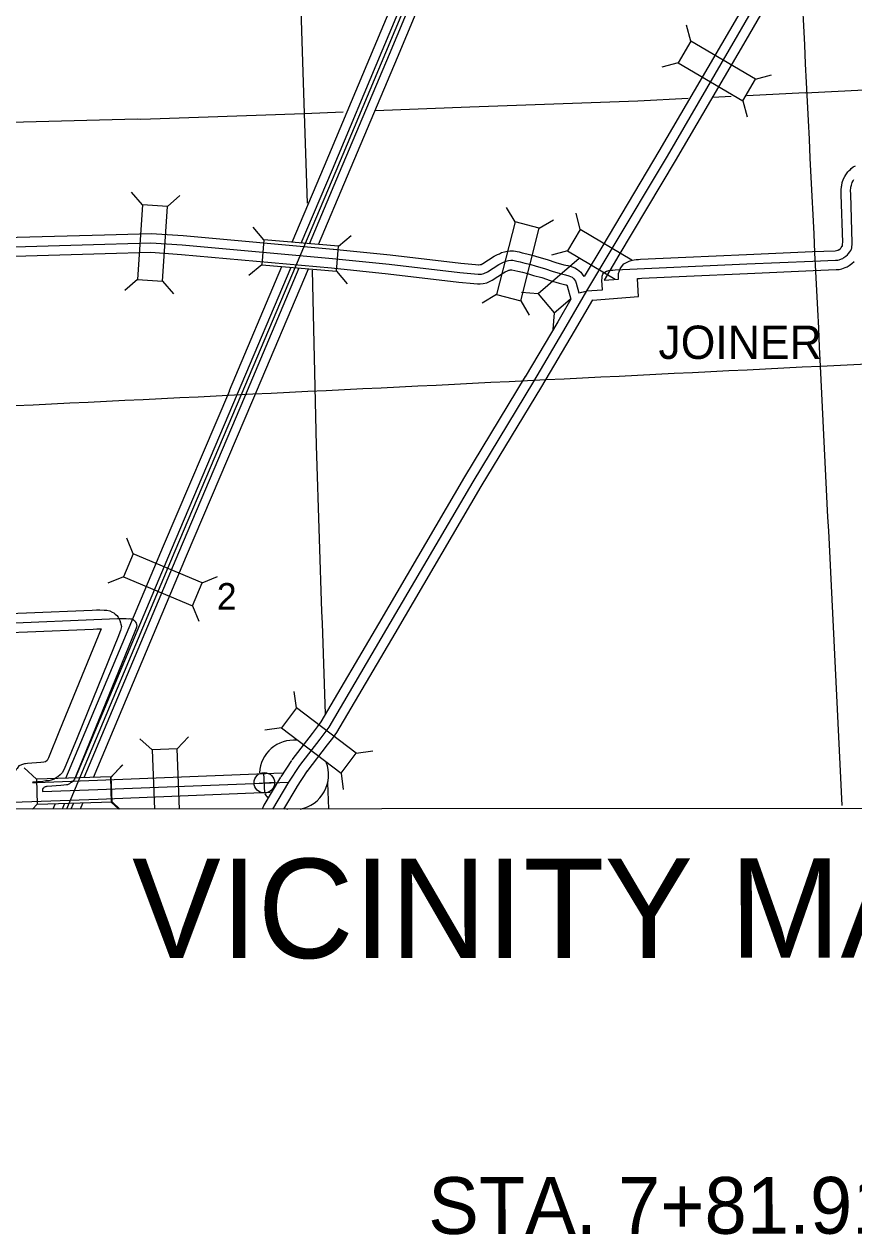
# Model space of a CAD drawing. Extents: x 2520745 to 2582119, y -1491628 to -1461664.
# Drawn here: x 2524549 to 2528934, y -1474299 to -1467904 of the extents above; entities that cross this region are included whole.
import ezdxf

# ---------------------------------------------------------------- set-up
doc = ezdxf.new("R2010")
doc.units = 0
for name, color, linetype in [('1', 7, 'Continuous'), ('10', 7, 'Continuous'), ('15', 7, 'Continuous'), ('19', 7, 'Continuous'), ('20', 7, 'Continuous'), ('24', 7, 'Continuous'), ('26', 7, 'Continuous'), ('4', 7, 'Continuous'), ('59', 7, 'Continuous'), ('6', 7, 'Continuous'), ('60', 7, 'Continuous'), ('R_Draft', 7, 'Continuous')]:
    doc.layers.add(name, color=color, linetype=linetype)

msp = doc.modelspace()

# ---------------------------------------------------------------- linework, layer by layer
at = {"layer": '1'}
msp.add_lwpolyline([(2520744.9, -1463342.8), (2532121.5, -1463335.8), (2532126.8, -1472046.5), (2520750.2, -1472053.4)], close=True, dxfattribs=at)
at = {"layer": '10'}
for points in [[(2528716, -1469105.2), (2528835.2, -1469100.9), (2528842.2, -1469100.4), (2528843.4, -1469100.1), (2528850.9, -1469097.5), (2528852.2, -1469096.8), (2528854.5, -1469095.5), (2528861.8, -1469090), (2528865.1, -1469087.4), (2528867.7, -1469084.1), (2528873.4, -1469077.2), (2528873.7, -1469076.8), (2528874, -1469073.3), (2528875.2, -1469065), (2528875.8, -1469058), (2528867.8, -1468803.4), (2528866.8, -1468780.4), (2528869, -1468761.6), (2528870.1, -1468756.1), (2528872.7, -1468741.2), (2528880.5, -1468720.8), (2528886.2, -1468709.6), (2528891.2, -1468699.1), (2528903, -1468683.6), (2528910.2, -1468676.4), (2528915.8, -1468671.2), (2528921, -1468666.7), (2528930.7, -1468658.4), (2528943.4, -1468652.4)], [(2524312.7, -1469035.1), (2524973.8, -1469016.2), (2525219.5, -1469009.1), (2525388.5, -1469020.3), (2526182.9, -1469091.8)], [(2526183.5, -1469091.9), (2526483.8, -1469122.7), (2526857.3, -1469166.7), (2526934.6, -1469173.7), (2526950.4, -1469175.4), (2526952.3, -1469175.4), (2526959.3, -1469174.5), (2526963.6, -1469173.7), (2526973.3, -1469169.2), (2527032.6, -1469129.5), (2527051.1, -1469121), (2527061.6, -1469116.5), (2527072.5, -1469111), (2527088.4, -1469105.9), (2527102.2, -1469103.1), (2527116.9, -1469101.6), (2527136, -1469100.8), (2527164.7, -1469107.2), (2527182, -1469111.6), (2527205.9, -1469117.4), (2527234.7, -1469124), (2527270, -1469135), (2527313.9, -1469147.3), (2527359.6, -1469162.2), (2527401.8, -1469174.8), (2527422.7, -1469179.7), (2527444.7, -1469185.7), (2527459.1, -1469191.6), (2527473.2, -1469200), (2527482.8, -1469207.7), (2527490.7, -1469215), (2527498.6, -1469224.2), (2527506.9, -1469236.8)], [(2528045.5, -1469135.3), (2528367, -1469120.5), (2528715.6, -1469105.2)], [(2524315.9, -1469135.1), (2524976.7, -1469116.1), (2525217.6, -1469109.2), (2525380.7, -1469120), (2526174, -1469191.4)], [(2527690.2, -1469250.9), (2527690.8, -1469238), (2527690.7, -1469221.2), (2527695.8, -1469206.5), (2527699.7, -1469197), (2527706, -1469185.4), (2527717.9, -1469170.9), (2527732.4, -1469162.9), (2527747.4, -1469155.9), (2527756.9, -1469153.3), (2527763.7, -1469151.3), (2527772.7, -1469149.5), (2527783.8, -1469147.5), (2527795.5, -1469147), (2527807, -1469146.2), (2528045.5, -1469135.3)], [(2528719.7, -1469205.1), (2528840.5, -1469200.8), (2528856.1, -1469199.6), (2528870.7, -1469196.6), (2528888.8, -1469190.1), (2528898.5, -1469185.6), (2528910, -1469179), (2528923.3, -1469168.9), (2528936.7, -1469158.1)], [(2526173.3, -1469191.3), (2526472.8, -1469222.1), (2526846.9, -1469266.2), (2526924.8, -1469273.3), (2526945.1, -1469275.4), (2526958.6, -1469275.4), (2526974.7, -1469273.3), (2526994.2, -1469269.8), (2527022.5, -1469256.6), (2527081.7, -1469217), (2527092, -1469212.3), (2527103.8, -1469207.2), (2527110.4, -1469203.8), (2527113.6, -1469202.8), (2527117.1, -1469202.1), (2527124.2, -1469201.4), (2527127.1, -1469201.3), (2527141.5, -1469204.5), (2527157.8, -1469208.6), (2527183, -1469214.8), (2527208.8, -1469220.6), (2527241.7, -1469230.9), (2527284.8, -1469243), (2527329.7, -1469257.7), (2527375.9, -1469271.4), (2527398.1, -1469276.7), (2527412.5, -1469280.6), (2527414.3, -1469281.3), (2527416, -1469282.3), (2527417.5, -1469283.5), (2527418.4, -1469284.3), (2527418.9, -1469286.1), (2527437.9, -1469357)], [(2527795.6, -1469343.4), (2527790.3, -1469250.2), (2527790.4, -1469247.9), (2527791.4, -1469247.7), (2527794.8, -1469247.1), (2527801.1, -1469246.8), (2527812.8, -1469246), (2528050.1, -1469235.2)], [(2528050.1, -1469235.2), (2528371.5, -1469220.4), (2528720, -1469205.1)], [(2527615.3, -1469256.5), (2527690.2, -1469250.9)], [(2527553.5, -1469361.3), (2527795.6, -1469343.4)], [(2522613.1, -1471078.5), (2523482, -1471051.5), (2524373.6, -1471021.4), (2524561.8, -1471013.8)], [(2524561.8, -1471013.8), (2524907.8, -1470999.7), (2524931.4, -1470998.2), (2524948.3, -1470998.6), (2524971.7, -1470999.3), (2524985.2, -1471000.6), (2525001.5, -1471003.3), (2525014.7, -1471009.6), (2525023, -1471014.1), (2525029.6, -1471020.1), (2525037.5, -1471026.8), (2525037.9, -1471027.3)], [(2525037.9, -1471027.3), (2525045.1, -1471036.6), (2525049.5, -1471044), (2525055.1, -1471054), (2525058.7, -1471066.1), (2525059.9, -1471073.4), (2525062.8, -1471086.8), (2525058.3, -1471108), (2525055.3, -1471116.7), (2525048.2, -1471135.4), (2524828.6, -1471674)], [(2522605.7, -1471178.8), (2523485.2, -1471151.5), (2524377.3, -1471121.3), (2524565.9, -1471113.7)], [(2524565.9, -1471113.7), (2524912.9, -1471099.6), (2524933.3, -1471098.3), (2524941.3, -1471098.5)], [(2524941.3, -1471098.5), (2524945.8, -1471098.6), (2524953, -1471098.8), (2524955.1, -1471099), (2524736, -1471636.2)], [(2524736, -1471636.2), (2524677.3, -1471779.9), (2524671.2, -1471794.5), (2524662.1, -1471801.8), (2524653.3, -1471802.2), (2524636.1, -1471804.7), (2524566.2, -1471809.6), (2524556.7, -1471810.7), (2524550.6, -1471812.3), (2524544.8, -1471813.8), (2524521.2, -1471822.9), (2524511.7, -1471836.1), (2524506.6, -1471841.6), (2524498.2, -1471857.7), (2524495.2, -1471872.7), (2524489.4, -1472014.5)], [(2524828.6, -1471674), (2524769.7, -1471818.2), (2524758.9, -1471844), (2524749.6, -1471858.4), (2524739.8, -1471869.2), (2524726.4, -1471880), (2524721, -1471882.7), (2524717.9, -1471885.2), (2524706.7, -1471892.8), (2524691.8, -1471898), (2524679.7, -1471901), (2524662.9, -1471901.8), (2524646.9, -1471904.2), (2524593.8, -1471907.9), (2524593.7, -1471910.7)], [(2524593.7, -1471910.7), (2524613.6, -1471910)], [(2524613.6, -1471910), (2524936.4, -1471898.4)], [(2524936.4, -1471897.8), (2525913.3, -1471859.2)], [(2524940.3, -1471997.7), (2525849.7, -1471961.8)], [(2524940.3, -1471997.7), (2525849.7, -1471961.8)], [(2524489.4, -1472014.5), (2524940.3, -1471998.4)]]:
    msp.add_lwpolyline(points, dxfattribs=at)
at = {"layer": '15'}
for points in [[(2528611.7, -1467485.9), (2528591.4, -1467507), (2528560.4, -1467530.3), (2528535.5, -1467557.2), (2528516, -1467575.6), (2528500.1, -1467592.7), (2528489.1, -1467606.8), (2528479, -1467617.8), (2528467, -1467630.1), (2528456.5, -1467645.9), (2528437.5, -1467669.6), (2528417.6, -1467701.3), (2528398.1, -1467729.3), (2528373.7, -1467769.9), (2528276.4, -1467937.9), (2527904, -1468575.1), (2527606.8, -1469072.4), (2527508.7, -1469237.9)], [(2528679.6, -1467559.6), (2528657.9, -1467582.1), (2528627.6, -1467604.9), (2528606.6, -1467627.5), (2528587, -1467646.1), (2528576.2, -1467657.7), (2528565.7, -1467671.3), (2528551.6, -1467686.6), (2528545.1, -1467693.2), (2528537.4, -1467704.9), (2528519.1, -1467727.7), (2528501, -1467756.5), (2528482.1, -1467783.6), (2528459.9, -1467820.7), (2528362.9, -1467988.2), (2527990.1, -1468625.9), (2527692.7, -1469123.5), (2527614.3, -1469255.9)], [(2527438.5, -1469357.3), (2527369.3, -1469475.8), (2527197.5, -1469766.4)], [(2527552.4, -1469360.6), (2527455.5, -1469526.5), (2527283.6, -1469817.3)], [(2527197.8, -1469766), (2526877.1, -1470295.9), (2526421.6, -1471072.2), (2526116.6, -1471590.5), (2526098.1, -1471616.1), (2526071.6, -1471651.2), (2525964.1, -1471790.3)], [(2527283.3, -1469817.7), (2526963, -1470347.1), (2526507.8, -1471122.8), (2526200.5, -1471645.1), (2526178.6, -1471675.5), (2526151, -1471712), (2526043.2, -1471851.4)], [(2525961.8, -1471793.5), (2525904.9, -1471880.6)], [(2526045.5, -1471848.2), (2525988.6, -1471935.3)], [(2525903.8, -1471882.4), (2525815.9, -1472030.1), (2525806.5, -1472050.3)], [(2525989.7, -1471933.5), (2525920.3, -1472050.2)]]:
    msp.add_lwpolyline(points, dxfattribs=at)
at = {"layer": '19'}
for points in [[(2526601.4, -1467541), (2526396.7, -1468029.5), (2526134, -1468654.9), (2525963.6, -1469058.2)], [(2526652.2, -1467538.3), (2526439, -1468047.3), (2526176.2, -1468672.7), (2526011.7, -1469062.2)], [(2526698.4, -1467535.8), (2526477.4, -1468063.4), (2526214.6, -1468688.9), (2526055.3, -1469065.9)], [(2526749.3, -1467533.1), (2526519.7, -1468081.1), (2526256.8, -1468706.7), (2526103.4, -1469069.9)], [(2525909.6, -1469186.1), (2525633.2, -1469840.5)], [(2525957.6, -1469190.2), (2525675.4, -1469858.3)], [(2526001.3, -1469193.8), (2525713.8, -1469874.6)], [(2526049.4, -1469197.9), (2525756, -1469892.4)], [(2525633.3, -1469840.3), (2525283.1, -1470662.4), (2524768.1, -1471889.2)], [(2525675.4, -1469858.3), (2525325.3, -1470680.2), (2524819, -1471886.4)], [(2525713.8, -1469874.6), (2525363.7, -1470696.4), (2524865, -1471884.6)], [(2525755.9, -1469892.6), (2525405.9, -1470714.3), (2524914.3, -1471885.5)], [(2524710.5, -1472026.5), (2524700.2, -1472051)], [(2524760.8, -1472025.1), (2524749.9, -1472051)], [(2524807.1, -1472022.3), (2524795.1, -1472050.9)], [(2524857.2, -1472021.5), (2524844.8, -1472050.9)]]:
    msp.add_lwpolyline(points, dxfattribs=at)
at = {"layer": '20'}
for p, q in [((2528072, -1467994.4), (2528049.7, -1467909.3)), ((2528005.4, -1468108.4), (2527920.2, -1468130.7)), ((2528413.9, -1468194.2), (2528499, -1468171.9)), ((2528347.3, -1468308.2), (2528369.6, -1468393.3)), ((2525174.1, -1468857.8), (2525116.1, -1468791.6)), ((2525305.8, -1468866.5), (2525372, -1468808.5)), ((2527143.6, -1468949), (2527098.8, -1468873.3)), ((2527488.5, -1468988.5), (2527466.7, -1468903.3)), ((2525815.4, -1469043.4), (2525758.6, -1468976.2)), ((2527271.5, -1468981.7), (2527347.2, -1468936.8)), ((2526210, -1469076.6), (2526277.2, -1469019.8)), ((2527488.5, -1468988.5), (2527421.2, -1469102.1)), ((2527761.3, -1469150.1), (2527488.5, -1468988.5)), ((2527421.2, -1469102.1), (2527336, -1469123.9)), ((2527421.2, -1469102.1), (2527673.1, -1469251.3)), ((2527483.3, -1469142.1), (2527265.3, -1469328.2)), ((2525804.4, -1469175), (2525737.2, -1469231.8)), ((2526199, -1469208.1), (2526255.8, -1469275.3)), ((2525147.8, -1469252.9), (2525081.6, -1469310.9)), ((2525279.6, -1469261.6), (2525337.5, -1469327.9)), ((2527045.6, -1469332.7), (2526969.9, -1469377.6)), ((2527265.3, -1469328.2), (2527177.6, -1469321.3)), ((2527265.3, -1469328.2), (2527351, -1469428.6)), ((2527351, -1469428.6), (2527434.2, -1469357.6)), ((2527173.5, -1469365.4), (2527218.4, -1469441.1)), ((2527351, -1469428.6), (2527344.1, -1469516.3)), ((2525124.3, -1470701.3), (2525091.1, -1470619.8)), ((2525073.3, -1470823), (2524991.8, -1470856.3)), ((2525489.5, -1470854.6), (2525570.9, -1470821.3)), ((2525438.4, -1470976.3), (2525471.7, -1471057.7)), ((2525988.5, -1471516), (2525976.6, -1471428.9)), ((2525908.6, -1471621.2), (2525821.4, -1471633.1)), ((2525225, -1471738.3), (2525160.3, -1471678.6)), ((2525356.9, -1471733.1), (2525416.6, -1471668.4)), ((2526303.8, -1471755.6), (2526391, -1471743.7)), ((2524613.6, -1471892.7), (2524549.5, -1471832.4)), ((2525006.5, -1471882.9), (2525066.8, -1471818.9)), ((2525009.5, -1471880.5), (2525069.7, -1471816.4)), ((2525010.5, -1472014.9), (2525006.5, -1471882.9)), ((2526223.9, -1471860.7), (2526235.8, -1471947.9)), ((2524617.7, -1472024.6), (2524592.9, -1472051)), ((2525010.5, -1472014.9), (2525048.6, -1472050.8)), ((2525013.5, -1472012.4), (2525054.3, -1472050.8))]:
    msp.add_line(p, q, dxfattribs=at)
for points in [[(2528005.4, -1468108.4), (2528347.3, -1468308.2), (2528413.9, -1468194.2), (2528072, -1467994.4)], [(2525279.6, -1469261.6), (2525305.8, -1468866.5), (2525174.1, -1468857.8), (2525147.8, -1469252.9)], [(2527173.5, -1469365.4), (2527271.5, -1468981.7), (2527143.6, -1468949), (2527045.6, -1469332.7)], [(2526210, -1469076.6), (2525815.4, -1469043.4), (2525804.4, -1469175), (2526199, -1469208.1)], [(2525073.3, -1470823), (2525438.4, -1470976.3), (2525489.5, -1470854.6), (2525124.3, -1470701.3)], [(2525908.6, -1471621.2), (2526223.9, -1471860.7), (2526303.8, -1471755.6), (2525988.5, -1471516)], [(2525009.5, -1471880.5), (2524613.6, -1471892.7), (2524617.7, -1472024.6), (2525013.5, -1472012.4)]]:
    msp.add_lwpolyline(points, close=True, dxfattribs=at)
msp.add_lwpolyline([(2525369.4, -1472050.6), (2525356.9, -1471733.1), (2525225, -1471738.3), (2525237.3, -1472050.7)], dxfattribs=at)
at = {"layer": '24'}
for centre, radius, start, end in [((2525974, -1471868.6), 182.1, 84.98379, 176.76004), ((2525974.4, -1471869.8), 183.3, 280.27222, 21.61478), ((2525974.4, -1471869.8), 183.3, 212.96479, 220.79458), ((2525974.4, -1471869.8), 183.3, 255.72233, 259.79766)]:
    msp.add_arc(centre, radius, start, end, dxfattribs=at)
at = {"layer": '26'}
for p, q in [((2525821.5, -1471965.8), (2525814.9, -1471857.7)), ((2525764.1, -1471915.1), (2525872.3, -1471908.4))]:
    msp.add_line(p, q, dxfattribs=at)
msp.add_circle((2525818.2, -1471911.8), 54.2, dxfattribs=at)
at = {"layer": '4'}
for points in [[(2525852, -1463339.6), (2525878.6, -1463966.7), (2525910.6, -1464848.3), (2525942.6, -1465736.3), (2525969.7, -1466605.8), (2526000.9, -1467499.5), (2526028.8, -1468376.3), (2526045.2, -1468850.4)], [(2528677.2, -1468267.1), (2529546.6, -1468223.4), (2529563.9, -1468222.3), (2530426.9, -1468182.8), (2530457.7, -1468179.2), (2531300, -1468116.8)], [(2528677.2, -1468267.1), (2528368.2, -1468282.2)], [(2528057.8, -1468297.3), (2527792.7, -1468310.3), (2526904.1, -1468343.3), (2526403.9, -1468362.7)], [(2528286.5, -1468286.2), (2528189.8, -1468290.9)], [(2526235.8, -1468369.3), (2526028.1, -1468377.4), (2525166, -1468406.9), (2525148, -1468405.7), (2524276.2, -1468427.9), (2523411.1, -1468458.6), (2523388.2, -1468459.5), (2522558.3, -1468486.6)], [(2526071.5, -1469203.9), (2526092.3, -1470129.6), (2526108.5, -1470622.1)], [(2526108.5, -1470622.1), (2526121.2, -1471006.2), (2526123.4, -1471067.8)], [(2526123.4, -1471067.8), (2526140.1, -1471549.2)], [(2526152.8, -1471912.2), (2526157.8, -1472050.1)]]:
    msp.add_lwpolyline(points, dxfattribs=at)
at = {"layer": '59'}
for points in [[(2528477.1, -1464033.8), (2528058, -1464834.2), (2527713.6, -1465492.9), (2527395.6, -1466100), (2527126.2, -1466610), (2526863, -1467117), (2526737.9, -1467387.6), (2526458.2, -1468055.3), (2526195.4, -1468680.8), (2525694.6, -1469866.4)], [(2528645.7, -1467522.7), (2528624.7, -1467544.5), (2528594, -1467567.6), (2528571.1, -1467592.3), (2528551.5, -1467610.9), (2528538.1, -1467625.2), (2528527.4, -1467639), (2528515.3, -1467652.2), (2528506, -1467661.7), (2528497, -1467675.4), (2528478.3, -1467698.6), (2528459.3, -1467728.9), (2528440.1, -1467756.5), (2528416.8, -1467795.3), (2528319.7, -1467963), (2527947, -1468600.5), (2527649.8, -1469097.9), (2527522, -1469313.5)], [(2528645.7, -1467522.7), (2528624.7, -1467544.5), (2528594, -1467567.6), (2528571.1, -1467592.3), (2528551.5, -1467610.9), (2528538.1, -1467625.2), (2528527.4, -1467639), (2528515.3, -1467652.2), (2528506, -1467661.7), (2528497, -1467675.4), (2528478.3, -1467698.6), (2528459.3, -1467728.9), (2528440.1, -1467756.5), (2528416.8, -1467795.3), (2528319.7, -1467963), (2527947, -1468600.5), (2527649.8, -1469097.9), (2527522, -1469313.5)], [(2528717.8, -1469155.2), (2528837.8, -1469150.8), (2528849.1, -1469150), (2528857, -1469148.3), (2528869.8, -1469143.8), (2528875.4, -1469141.2), (2528882.2, -1469137.2), (2528892.5, -1469129.4), (2528900.9, -1469122.7), (2528906.6, -1469115.5), (2528913.2, -1469107.5), (2528918.3, -1469100.2), (2528922.2, -1469090.7), (2528923, -1469086.6), (2528923.7, -1469079.3), (2528925, -1469070.5), (2528925.8, -1469059.1), (2528917.8, -1468801.6), (2528917, -1468782.2), (2528918.4, -1468769.4), (2528919.2, -1468765.3), (2528921.1, -1468754.5), (2528926.2, -1468741.3), (2528931.1, -1468731.7), (2528934.2, -1468725.2)], [(2528717.8, -1469155.2), (2528837.8, -1469150.8), (2528849.1, -1469150), (2528857, -1469148.3), (2528869.8, -1469143.8), (2528875.4, -1469141.2), (2528882.2, -1469137.2), (2528892.5, -1469129.4), (2528900.9, -1469122.7), (2528906.6, -1469115.5), (2528913.2, -1469107.5), (2528918.3, -1469100.2), (2528922.2, -1469090.7), (2528923, -1469086.6), (2528923.7, -1469079.3), (2528925, -1469070.5), (2528925.8, -1469059.1), (2528917.8, -1468801.6), (2528917, -1468782.2), (2528918.4, -1468769.4), (2528919.2, -1468765.3), (2528921.1, -1468754.5), (2528926.2, -1468741.3), (2528931.1, -1468731.7), (2528934.2, -1468725.2)], [(2524314.3, -1469085.1), (2524975.3, -1469066.1), (2525218.6, -1469059.2), (2525384.6, -1469070.2), (2526178.4, -1469141.6)], [(2524314.3, -1469085.1), (2524975.3, -1469066.1), (2525218.6, -1469059.2), (2525384.6, -1469070.2), (2526178.4, -1469141.6)], [(2526178.4, -1469141.6), (2526478.3, -1469172.4), (2526852.1, -1469216.4), (2526929.7, -1469223.5), (2526947.8, -1469225.4), (2526955.4, -1469225.4), (2526967, -1469223.9), (2526978.9, -1469221.8), (2526997.9, -1469212.9), (2527057.2, -1469173.3), (2527071.5, -1469166.6), (2527082.7, -1469161.8), (2527091.5, -1469157.4), (2527101, -1469154.3), (2527109.6, -1469152.6), (2527120.5, -1469151.5), (2527131.5, -1469151), (2527153.1, -1469155.8), (2527169.9, -1469160.1), (2527194.5, -1469166.1), (2527221.7, -1469172.3), (2527255.8, -1469182.9), (2527299.4, -1469195.1), (2527344.6, -1469209.9), (2527388.9, -1469223.1), (2527410.4, -1469228.2), (2527428.6, -1469233.1), (2527436.7, -1469236.5), (2527444.6, -1469241.2), (2527450.1, -1469245.6), (2527454.6, -1469249.8), (2527458.5, -1469254.3), (2527463.8, -1469262.4), (2527466.9, -1469272), (2527480.8, -1469323.9), (2527520.8, -1469313.8)], [(2526178.4, -1469141.6), (2526478.3, -1469172.4), (2526852.1, -1469216.4), (2526929.7, -1469223.5), (2526947.8, -1469225.4), (2526955.4, -1469225.4), (2526967, -1469223.9), (2526978.9, -1469221.8), (2526997.9, -1469212.9), (2527057.2, -1469173.3), (2527071.5, -1469166.6), (2527082.7, -1469161.8), (2527091.5, -1469157.4), (2527101, -1469154.3), (2527109.6, -1469152.6), (2527120.5, -1469151.5), (2527131.5, -1469151), (2527153.1, -1469155.8), (2527169.9, -1469160.1), (2527194.5, -1469166.1), (2527221.7, -1469172.3), (2527255.8, -1469182.9), (2527299.4, -1469195.1), (2527344.6, -1469209.9), (2527388.9, -1469223.1), (2527410.4, -1469228.2), (2527428.6, -1469233.1), (2527436.7, -1469236.5), (2527444.6, -1469241.2), (2527450.1, -1469245.6), (2527454.6, -1469249.8), (2527458.5, -1469254.3), (2527463.8, -1469262.4), (2527466.9, -1469272), (2527480.8, -1469323.9), (2527518.3, -1469314.4)], [(2527520.2, -1469314), (2527522, -1469313.5), (2527605.7, -1469306.6), (2527602.9, -1469256.9), (2527603.4, -1469245.1), (2527603.3, -1469235.8), (2527605.1, -1469230.7), (2527607.5, -1469224.9), (2527610.3, -1469219.7), (2527613.2, -1469216.3), (2527617.7, -1469213.7), (2527627.2, -1469209.3), (2527633.1, -1469207.7), (2527638.4, -1469206.2), (2527644.7, -1469204.9), (2527651.9, -1469203.6), (2527660.9, -1469203.2), (2527672.5, -1469202.4), (2528369.3, -1469170.5), (2528717.8, -1469155.2)], [(2527521.6, -1469313.6), (2527522, -1469313.5), (2527605.7, -1469306.6), (2527602.9, -1469256.9), (2527603.4, -1469245.1), (2527603.3, -1469235.8), (2527605.1, -1469230.7), (2527607.5, -1469224.9), (2527610.3, -1469219.7), (2527613.2, -1469216.3), (2527617.7, -1469213.7), (2527627.2, -1469209.3), (2527633.1, -1469207.7), (2527638.4, -1469206.2), (2527644.7, -1469204.9), (2527651.9, -1469203.6), (2527660.9, -1469203.2), (2527672.5, -1469202.4), (2528369.3, -1469170.5), (2528717.8, -1469155.2)], [(2527522, -1469313.5), (2527412.4, -1469501.2), (2527240.6, -1469791.9)], [(2527522, -1469313.5), (2527412.4, -1469501.2), (2527240.6, -1469791.9)], [(2527240.6, -1469791.9), (2526920, -1470321.5), (2526464.7, -1471097.5), (2526158.5, -1471617.8), (2526138.4, -1471645.8), (2526111.3, -1471681.6), (2526003.6, -1471820.9)], [(2527240.6, -1469791.9), (2526920, -1470321.5), (2526464.7, -1471097.5), (2526158.5, -1471617.8), (2526138.4, -1471645.8), (2526111.3, -1471681.6), (2526003.6, -1471820.9)], [(2525694.6, -1469866.4), (2525344.5, -1470688.3), (2524772.5, -1472050.9)], [(2522550.3, -1471130.5), (2523483.6, -1471101.5), (2524375.5, -1471071.4), (2525042.2, -1471044.3), (2525064.2, -1471042.9), (2525073.2, -1471043.1)], [(2525073.2, -1471043.1), (2525078.9, -1471043.2), (2525087.9, -1471043.5), (2525102, -1471044.9), (2525105.7, -1471044.4), (2525110.4, -1471044.8), (2525118.2, -1471046.1), (2525124, -1471048.9), (2525125.7, -1471049.8), (2525128.5, -1471052.4), (2525133, -1471056.2), (2525135.5, -1471059.4), (2525138, -1471063.6), (2525140.6, -1471068.2), (2525141.7, -1471072.2), (2525142.6, -1471077.5), (2525143.5, -1471081.5), (2525141.8, -1471089.2), (2525140.1, -1471094.4), (2525133.5, -1471111.7), (2524823.8, -1471871), (2524814.8, -1471892.5), (2524810.1, -1471899.8), (2524805.7, -1471904.7), (2524799.5, -1471909.6), (2524794.3, -1471912.2), (2524788.5, -1471916.8), (2524784.3, -1471919.7), (2524777.7, -1471922), (2524772.7, -1471923.3), (2524758.4, -1471923.9), (2524741.8, -1471926.4), (2524671.1, -1471931.3), (2524666.5, -1471931.8), (2524663.5, -1471932.7), (2524660.2, -1471933.5), (2524653.3, -1471936.1), (2524650.8, -1471939.6), (2524648.2, -1471942.4), (2524646.1, -1471946.5), (2524645.3, -1471950.6), (2524645, -1471958.3), (2524938.3, -1471947.8)], [(2526003.6, -1471820.9), (2525946.8, -1471907.9)], [(2526003.6, -1471820.9), (2525946.8, -1471907.9)], [(2524938.3, -1471947.8), (2525946.8, -1471907.9)], [(2525946.8, -1471907.9), (2525862.1, -1472050.3)]]:
    msp.add_lwpolyline(points, dxfattribs=at)
at = {"layer": '60'}
for points in [[(2528872.9, -1472031.2), (2528758.3, -1469710.2), (2528442.3, -1463321.7)], [(2520749.1, -1470099.6), (2522564.1, -1470012.5), (2528758.3, -1469710.2), (2532125.3, -1469542.5)]]:
    msp.add_spline(points, degree=3, dxfattribs=at)

# ---------------------------------------------------------------- texts
at = {"layer": '20'}
msp.add_text('2', height=140.8, dxfattribs=at).set_placement((2525567, -1470997.3))
at = {"layer": '6'}
msp.add_text('JOINER', height=176, dxfattribs=at).set_placement((2527901.7, -1469672.5))
at = {"layer": 'R_Draft'}
for s, height, p in [('VICINITY MAP', 525, (2525120, -1472838.2)), ('STA. 7+81.91', 300, (2526684.5, -1474295.2))]:
    msp.add_text(s, height=height, rotation=0.03494, dxfattribs=at).set_placement(p)

doc.saveas('drawing.dxf')
